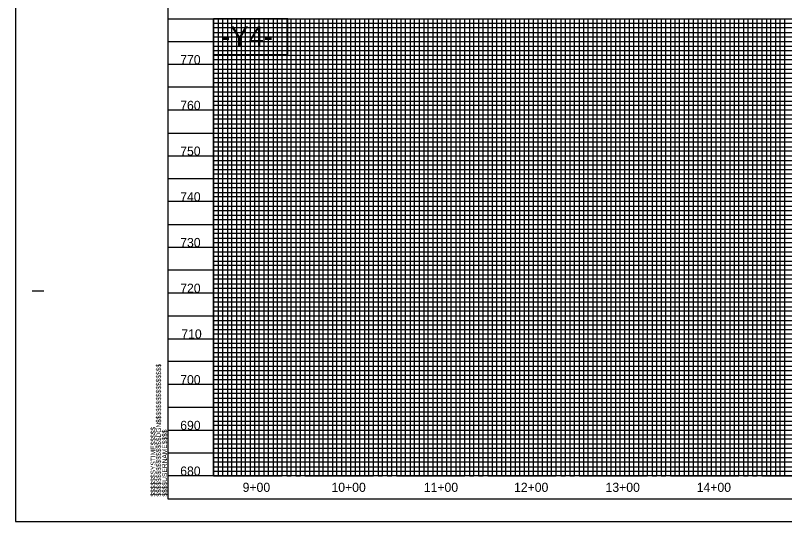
# Model space of a CAD drawing. Extents: x 1524869 to 1526553, y 501099 to 502199.
# Drawn here: x 1524869 to 1525711, y 501099 to 501652 of the extents above; entities that cross this region are included whole.
import ezdxf

# ---------------------------------------------------------------- set-up
doc = ezdxf.new("R2010")
doc.units = 0
for name, color, linetype in [('Exist Vertical Profile Horizontal Axis Label Major', 7, 'Continuous'), ('Exist Vertical Profile Vertical Axis Label', 7, 'Continuous'), ('Prop Grid Mask', 7, 'Continuous'), ('Prop Horizontal Alignment Curve and Spiral Data', 7, 'Continuous'), ('Sheet DOT Grid CELL', 7, 'Continuous'), ('Sheet Layout Profile Border Port 2', 7, 'Continuous'), ('Sheet Plot Border Outside CELL', 7, 'Continuous'), ('Sheet Profile CELL', 7, 'Continuous'), ('Sheet Profile Grid Major CELL', 7, 'Continuous'), ('Sheet Profile Grid Middle CELL', 7, 'Continuous'), ('Sheet Profile Grid Minor CELL', 7, 'Continuous')]:
    doc.layers.add(name, color=color, linetype=linetype)

msp = doc.modelspace()

# ---------------------------------------------------------------- linework, layer by layer
at = {"layer": 'Prop Grid Mask'}
msp.add_lwpolyline([(1525086.08, 501609.52), (1525167.19, 501609.52), (1525167.19, 501648.56), (1525086.08, 501648.56)], close=True, dxfattribs=at)
at = {"layer": 'Sheet DOT Grid CELL'}
msp.add_line((1525036.08, 501648.56), (1526535.97, 501648.56), dxfattribs=at)
at = {"layer": 'Sheet Layout Profile Border Port 2'}
msp.add_lwpolyline([(1525086.08, 501648.56), (1526486.08, 501648.56), (1526486.08, 501148.56), (1525086.08, 501148.56)], close=True, dxfattribs=at)
at = {"layer": 'Sheet Plot Border Outside CELL'}
msp.add_lwpolyline([(1524869.08, 501098.56), (1526553.08, 501098.56), (1526553.08, 502198.56), (1524869.08, 502198.56)], close=True, dxfattribs=at)
at = {"layer": 'Sheet Profile CELL'}
for p, q in [((1525036.08, 501648.56), (1526536.08, 501648.56)), ((1524887.58, 501351.06), (1524900.08, 501351.06)), ((1526536.08, 501148.56), (1525036.08, 501148.56)), ((1525036.08, 501123.56), (1526536.08, 501123.56)), ((1525036.08, 501123.56), (1525036.08, 501123.56)), ((1525036.08, 501123.56), (1525036.08, 501123.56)), ((1525036.08, 501123.56), (1525036.08, 501123.56)), ((1525036.08, 501123.56), (1525036.08, 501123.56)), ((1525036.08, 501123.56), (1525036.08, 501123.56)), ((1525036.08, 501123.56), (1525036.08, 501123.56)), ((1525036.08, 501123.56), (1525036.08, 501123.56))]:
    msp.add_line(p, q, dxfattribs=at)
msp.add_lwpolyline([(1526536.08, 502173.56), (1525036.08, 502173.56), (1525036.08, 501123.56), (1526536.08, 501123.56)], close=True, dxfattribs=at)
msp.add_lwpolyline([(1525073.58, 501123.56), (1525073.58, 501123.56)], dxfattribs=at)
at = {"layer": 'Sheet Profile Grid Major CELL'}
for p, q in [((1525536.08, 501648.56), (1525586.08, 501648.56)), ((1525636.08, 501648.56), (1525686.08, 501648.56)), ((1525036.08, 501148.56), (1525036.08, 501148.56))]:
    msp.add_line(p, q, dxfattribs=at)
for points in [[(1525086.08, 501648.56), (1525086.08, 501148.56), (1525136.08, 501148.56), (1525136.08, 501648.56), (1525186.08, 501648.56), (1525186.08, 501148.56), (1525236.08, 501148.56), (1525236.08, 501648.56), (1525286.08, 501648.56), (1525286.08, 501148.56), (1525336.08, 501148.56), (1525336.08, 501648.56), (1525386.08, 501648.56), (1525386.08, 501148.56), (1525436.08, 501148.56), (1525436.08, 501648.56), (1525486.08, 501648.56), (1525486.08, 501148.56), (1525536.08, 501148.56), (1525536.08, 501648.56), (1525586.08, 501648.56), (1525586.08, 501148.56), (1525636.08, 501148.56), (1525636.08, 501648.56), (1525686.08, 501648.56), (1525686.08, 501148.56), (1525736.08, 501148.56)], [(1526536.08, 501598.56), (1525036.08, 501598.56)], [(1526536.08, 501548.56), (1525036.08, 501548.56), (1525036.08, 501498.56), (1526536.08, 501498.56)], [(1526536.08, 501448.56), (1525036.08, 501448.56), (1525036.08, 501398.56), (1526536.08, 501398.56)], [(1526536.08, 501348.56), (1525036.08, 501348.56), (1525036.08, 501298.56), (1526536.08, 501298.56)], [(1526536.08, 501248.56), (1525036.08, 501248.56), (1525036.08, 501248.56), (1525036.08, 501198.56), (1526536.08, 501198.56)], [(1526536.08, 501148.56), (1525036.08, 501148.56)]]:
    msp.add_lwpolyline(points, dxfattribs=at)
at = {"layer": 'Sheet Profile Grid Middle CELL'}
for points in [[(1525061.08, 501648.56), (1525111.08, 501648.56), (1525111.08, 501148.56), (1525161.08, 501148.56), (1525161.08, 501648.56), (1525211.08, 501648.56), (1525211.08, 501148.56), (1525261.08, 501148.56), (1525261.08, 501648.56), (1525311.08, 501648.56), (1525311.08, 501148.56), (1525361.08, 501148.56), (1525361.08, 501648.56), (1525411.08, 501648.56), (1525411.08, 501148.56), (1525461.08, 501148.56), (1525461.08, 501648.56), (1525511.08, 501648.56), (1525511.08, 501148.56), (1525561.08, 501148.56), (1525561.08, 501648.56), (1525611.08, 501648.56), (1525611.08, 501148.56), (1525661.08, 501148.56), (1525661.08, 501148.56), (1525661.08, 501648.56), (1525711.08, 501648.56), (1525711.08, 501148.56), (1525761.08, 501148.56)], [(1525036.08, 501623.56), (1526536.08, 501623.56)], [(1526536.08, 501573.56), (1525036.08, 501573.56), (1525036.08, 501523.56), (1526536.08, 501523.56)], [(1526536.08, 501473.56), (1525036.08, 501473.56), (1525036.08, 501423.56), (1526536.08, 501423.56)], [(1526536.08, 501373.56), (1525036.08, 501373.56), (1525036.08, 501323.56), (1526536.08, 501323.56)], [(1526536.08, 501273.56), (1525036.08, 501273.56), (1525036.08, 501223.56), (1526536.08, 501223.56)], [(1526536.08, 501173.56), (1525036.08, 501173.56)]]:
    msp.add_lwpolyline(points, dxfattribs=at)
at = {"layer": 'Sheet Profile Grid Minor CELL'}
for p, q in [((1525086.08, 501643.56), (1526486.08, 501643.56)), ((1526486.08, 501638.56), (1525086.08, 501638.56)), ((1525086.08, 501638.56), (1525086.08, 501638.56)), ((1525086.08, 501633.56), (1526486.08, 501633.56)), ((1526486.08, 501628.56), (1525086.08, 501628.56)), ((1525086.08, 501618.56), (1526486.08, 501618.56)), ((1526486.08, 501613.56), (1525086.08, 501613.56)), ((1525086.08, 501608.56), (1526486.08, 501608.56)), ((1526486.08, 501603.56), (1525086.08, 501603.56)), ((1525086.08, 501593.56), (1526486.08, 501593.56)), ((1526486.08, 501588.56), (1525086.08, 501588.56)), ((1525086.08, 501583.56), (1526486.08, 501583.56)), ((1526486.08, 501578.56), (1525086.08, 501578.56)), ((1525086.08, 501568.56), (1526486.08, 501568.56)), ((1526486.08, 501563.56), (1525086.08, 501563.56)), ((1525086.08, 501558.56), (1526486.08, 501558.56)), ((1526486.08, 501553.56), (1525086.08, 501553.56)), ((1525086.08, 501543.56), (1526486.08, 501543.56)), ((1526486.08, 501538.56), (1525086.08, 501538.56)), ((1525086.08, 501533.56), (1526486.08, 501533.56)), ((1526486.08, 501528.56), (1525086.08, 501528.56)), ((1525086.08, 501518.56), (1526486.08, 501518.56)), ((1526486.08, 501513.56), (1525086.08, 501513.56)), ((1525086.08, 501508.56), (1526486.08, 501508.56)), ((1526486.08, 501503.56), (1525086.08, 501503.56)), ((1525086.08, 501493.56), (1526486.08, 501493.56)), ((1526486.08, 501488.56), (1525086.08, 501488.56)), ((1525086.08, 501483.56), (1526486.08, 501483.56)), ((1526486.08, 501478.56), (1525086.08, 501478.56)), ((1525086.08, 501468.56), (1526486.08, 501468.56)), ((1526486.08, 501463.56), (1525086.08, 501463.56)), ((1525086.08, 501458.56), (1526486.08, 501458.56)), ((1526486.08, 501453.56), (1525086.08, 501453.71)), ((1525086.08, 501443.56), (1526486.08, 501443.56)), ((1526486.08, 501438.56), (1525086.08, 501438.56)), ((1525086.08, 501433.56), (1526486.08, 501433.56)), ((1526486.08, 501428.56), (1525086.08, 501428.56)), ((1525086.08, 501418.56), (1526486.08, 501418.56)), ((1526486.08, 501413.56), (1525086.08, 501413.56)), ((1525086.08, 501408.56), (1526486.08, 501408.56)), ((1526486.08, 501403.56), (1525086.08, 501403.56)), ((1525086.08, 501393.56), (1526486.08, 501393.56)), ((1526486.08, 501388.56), (1525086.08, 501388.56)), ((1525086.08, 501383.56), (1526486.08, 501383.56)), ((1526486.08, 501378.56), (1525086.08, 501378.56)), ((1525086.08, 501368.56), (1526486.08, 501368.56)), ((1526486.08, 501363.56), (1525086.08, 501363.56)), ((1525086.08, 501358.56), (1526486.08, 501358.56)), ((1526486.08, 501353.56), (1525086.08, 501353.56)), ((1525086.08, 501343.56), (1526486.08, 501343.56)), ((1526486.08, 501338.56), (1525086.08, 501338.56)), ((1525086.08, 501333.56), (1526486.08, 501333.56)), ((1526486.08, 501328.56), (1525086.08, 501328.56)), ((1525086.08, 501318.56), (1526486.08, 501318.56)), ((1526486.08, 501313.56), (1525086.08, 501313.56)), ((1525086.08, 501308.56), (1526486.08, 501308.56)), ((1526486.08, 501303.56), (1525086.08, 501303.56)), ((1525086.08, 501293.56), (1526486.08, 501293.56)), ((1526486.08, 501288.56), (1525086.08, 501288.56)), ((1525086.08, 501283.56), (1526486.08, 501283.56)), ((1526486.08, 501278.56), (1525086.08, 501278.56)), ((1525086.08, 501268.56), (1526486.08, 501268.56)), ((1526486.08, 501263.56), (1525086.08, 501263.56)), ((1525086.08, 501258.56), (1526486.08, 501258.56)), ((1526486.08, 501253.56), (1525086.08, 501253.56)), ((1525086.08, 501243.56), (1526486.08, 501243.56)), ((1526486.08, 501238.56), (1525086.08, 501238.56)), ((1525086.08, 501233.56), (1526486.08, 501233.56)), ((1526486.08, 501228.56), (1525086.08, 501228.56)), ((1525086.08, 501218.56), (1526486.08, 501218.56)), ((1526486.08, 501213.56), (1525086.08, 501213.56)), ((1525086.08, 501208.56), (1526486.08, 501208.56)), ((1526486.08, 501203.56), (1525086.08, 501203.56)), ((1525086.08, 501193.56), (1526486.08, 501193.56)), ((1526486.08, 501188.56), (1525086.08, 501188.56)), ((1525086.08, 501183.56), (1526486.08, 501183.56)), ((1526486.08, 501178.56), (1525086.08, 501178.56)), ((1525086.08, 501168.56), (1526486.08, 501168.56)), ((1526486.08, 501163.56), (1525086.08, 501163.56)), ((1525086.08, 501158.56), (1526486.08, 501158.56)), ((1525086.08, 501153.56), (1526486.08, 501153.56))]:
    msp.add_line(p, q, dxfattribs=at)
for points in [[(1525086.08, 501648.56), (1525091.08, 501648.56), (1525091.08, 501148.56), (1525096.08, 501148.56), (1525096.08, 501648.56), (1525101.08, 501648.56), (1525101.08, 501148.56), (1525106.08, 501148.56), (1525106.08, 501648.56), (1525116.08, 501648.56), (1525116.08, 501148.56), (1525121.08, 501148.56), (1525121.08, 501648.56), (1525126.08, 501648.56), (1525126.08, 501148.56), (1525131.08, 501148.56), (1525141.08, 501148.56), (1525146.08, 501148.56), (1525146.08, 501648.56), (1525151.08, 501648.56), (1525151.08, 501148.56), (1525156.08, 501148.56), (1525156.08, 501648.56), (1525166.08, 501648.56), (1525166.08, 501148.56), (1525171.08, 501148.56), (1525171.08, 501648.56), (1525176.08, 501648.56), (1525176.08, 501148.56), (1525181.08, 501148.56), (1525181.08, 501648.56), (1525191.08, 501648.56), (1525191.08, 501148.56), (1525196.08, 501148.56), (1525196.08, 501648.56), (1525201.08, 501648.56), (1525201.08, 501148.56), (1525206.08, 501148.56), (1525206.08, 501648.56), (1525216.08, 501648.56), (1525216.08, 501148.56), (1525221.08, 501148.56), (1525221.08, 501648.56), (1525226.08, 501648.56), (1525226.08, 501148.56), (1525231.08, 501148.56), (1525231.08, 501648.56), (1525241.08, 501648.56), (1525241.08, 501148.56), (1525246.08, 501148.56), (1525246.08, 501648.56), (1525251.08, 501648.56), (1525251.08, 501148.56), (1525256.08, 501148.56), (1525256.08, 501648.56), (1525266.08, 501648.56), (1525266.08, 501148.56), (1525271.08, 501148.56), (1525271.08, 501648.56), (1525276.08, 501648.56), (1525276.08, 501148.56), (1525281.08, 501148.56), (1525281.08, 501648.56), (1525291.08, 501648.56), (1525291.08, 501148.56), (1525296.08, 501148.56), (1525296.08, 501648.56), (1525301.08, 501648.56), (1525301.08, 501148.56)], [(1525131.08, 501148.56), (1525131.08, 501648.56), (1525141.08, 501648.56), (1525141.08, 501148.56)], [(1525301.08, 501148.56), (1525306.08, 501148.56), (1525306.08, 501648.56), (1525316.08, 501648.56), (1525316.08, 501148.56), (1525321.08, 501148.56), (1525321.08, 501648.56), (1525326.08, 501648.56), (1525326.08, 501148.56), (1525331.08, 501148.56), (1525331.08, 501648.56), (1525341.08, 501648.56), (1525341.08, 501148.56), (1525346.08, 501148.56), (1525346.08, 501648.56), (1525351.08, 501648.56), (1525351.08, 501148.56), (1525356.08, 501148.56), (1525356.08, 501648.56), (1525366.08, 501648.56), (1525366.08, 501148.56), (1525371.08, 501148.56), (1525371.08, 501648.56), (1525376.08, 501648.56), (1525376.08, 501148.56), (1525381.08, 501148.56), (1525381.08, 501648.56), (1525391.08, 501648.56), (1525391.08, 501148.56), (1525396.08, 501148.56), (1525396.08, 501648.56), (1525401.08, 501648.56), (1525401.08, 501148.56), (1525406.08, 501148.56), (1525406.08, 501648.56), (1525416.08, 501648.56), (1525416.08, 501148.56), (1525421.08, 501148.56), (1525421.08, 501648.56), (1525426.08, 501648.56), (1525426.08, 501148.56), (1525431.08, 501148.56), (1525431.08, 501648.56), (1525441.08, 501648.56), (1525441.08, 501148.56), (1525446.08, 501148.56), (1525446.08, 501648.56), (1525451.08, 501648.56), (1525451.08, 501148.56), (1525456.08, 501148.56), (1525456.08, 501648.56), (1525466.08, 501648.56), (1525466.08, 501148.56), (1525471.08, 501148.56), (1525471.08, 501648.56), (1525476.08, 501648.56), (1525476.08, 501148.56), (1525481.08, 501148.56), (1525481.08, 501648.56), (1525491.08, 501648.56), (1525491.08, 501148.56), (1525496.08, 501148.56), (1525496.08, 501648.56), (1525501.08, 501648.56), (1525501.08, 501148.56), (1525506.08, 501148.56), (1525506.08, 501648.56), (1525516.08, 501648.56), (1525516.08, 501148.56), (1525521.08, 501148.56), (1525521.08, 501648.56), (1525526.08, 501648.56), (1525526.08, 501148.56), (1525531.08, 501148.56), (1525531.08, 501648.56), (1525541.08, 501648.56), (1525541.08, 501148.56), (1525546.08, 501148.56), (1525546.08, 501648.56), (1525551.08, 501648.56), (1525551.08, 501148.56), (1525556.08, 501148.56), (1525556.08, 501648.56), (1525566.08, 501648.56), (1525566.08, 501148.56), (1525571.08, 501148.56), (1525571.08, 501648.56), (1525576.08, 501648.56), (1525576.08, 501148.56), (1525581.08, 501148.56), (1525581.08, 501648.56), (1525591.08, 501648.56), (1525591.08, 501148.56), (1525596.08, 501148.56), (1525596.08, 501648.56), (1525601.08, 501648.56), (1525601.08, 501148.56), (1525606.08, 501148.56), (1525606.08, 501648.56), (1525616.08, 501648.56)], [(1525616.08, 501648.56), (1525616.08, 501148.56), (1525621.08, 501148.56), (1525621.08, 501648.56), (1525626.08, 501648.56), (1525626.08, 501148.56), (1525631.08, 501148.56), (1525631.08, 501648.56), (1525641.08, 501648.56), (1525641.08, 501148.56), (1525646.08, 501148.56), (1525646.08, 501648.56), (1525651.08, 501648.56), (1525651.08, 501148.56), (1525656.08, 501148.56), (1525656.08, 501648.56), (1525666.08, 501648.56), (1525666.08, 501148.56), (1525671.08, 501148.56), (1525671.08, 501648.56), (1525676.08, 501648.56), (1525676.08, 501148.56), (1525681.08, 501148.56), (1525681.08, 501648.56), (1525691.08, 501648.56), (1525691.08, 501148.56), (1525696.08, 501148.56), (1525696.08, 501648.56), (1525701.08, 501648.56), (1525701.08, 501148.56), (1525706.08, 501148.56), (1525706.08, 501648.56), (1525716.08, 501648.56)]]:
    msp.add_lwpolyline(points, dxfattribs=at)

# ---------------------------------------------------------------- texts
at = {"layer": 'Exist Vertical Profile Horizontal Axis Label Major'}
for s, p in [('9+00', (1525117.83, 501131.06)), ('10+00', (1525215.07, 501131.06)), ('11+00', (1525316.13, 501131.06)), ('12+00', (1525414.91, 501131.06)), ('13+00', (1525515.07, 501131.06)), ('14+00', (1525614.86, 501131.06))]:
    msp.add_text(s, height=10, dxfattribs=at).set_placement(p)
at = {"layer": 'Exist Vertical Profile Vertical Axis Label'}
for s, p in [('770', (1525049.51, 501598.81)), ('760', (1525049.51, 501548.81)), ('750', (1525049.51, 501498.81)), ('740', (1525049.51, 501448.81)), ('730', (1525049.51, 501398.81)), ('720', (1525049.51, 501348.81)), ('710', (1525050.71, 501298.81)), ('700', (1525049.51, 501248.81)), ('690', (1525049.51, 501198.81)), ('680', (1525049.51, 501148.81))]:
    msp.add_text(s, height=10, dxfattribs=at).set_placement(p)
at = {"layer": 'Prop Horizontal Alignment Curve and Spiral Data'}
msp.add_text('-Y4-', height=22.5, rotation=360, dxfattribs=at).set_placement((1525094.28, 501617.79))
at = {"layer": 'Sheet Profile CELL'}
for s, p in [('$$$$$$$$$$$$$$$$DGN$$$$$$$$$$$$$$$$', (1525028.44, 501125.94)), ('$$$$$$SYSTIME$$$$$', (1525022.39, 501125.94)), ('$$$$USERNAME$$$$', (1525035.02, 501125.95))]:
    msp.add_text(s, height=5.25, rotation=90, dxfattribs=at).set_placement(p)

doc.saveas('drawing.dxf')
